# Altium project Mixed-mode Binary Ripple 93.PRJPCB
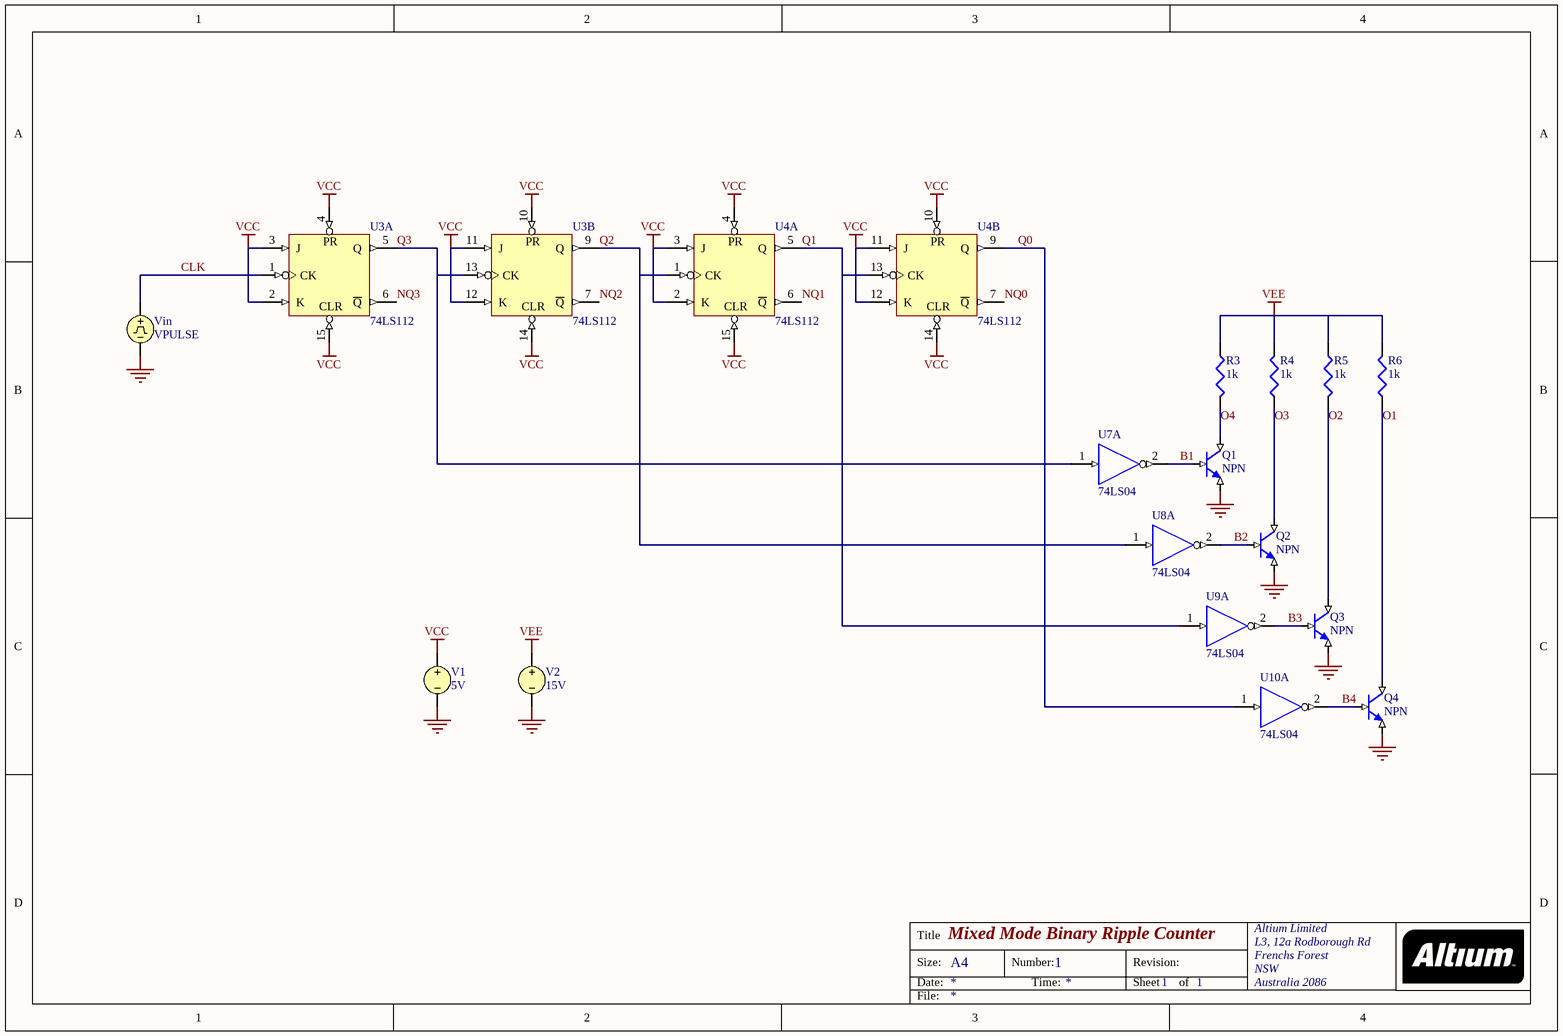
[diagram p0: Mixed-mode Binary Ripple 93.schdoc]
1 sheet, 17 parts. Net scope: global (net labels, ports and power ports of the same name join across sheets).

## Sheet Mixed-mode Binary Ripple 93.schdoc: Mixed Mode Binary Ripple Counter
size A4; Organization: Altium Limited; Address1: L3, 12a Rodborough Rd; Address2: Frenchs Forest; Address3: NSW; Address4: Australia 2086; DocumentNumber: 1; SheetNumber: 1; SheetTotal: 1

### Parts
Q1  NPN
Q2  NPN
Q3  NPN
Q4  NPN
R3  1k
R4  1k
R5  1k
R6  1k
U3  74LS112  (parts A,B of 2)
U4  74LS112  (parts A,B of 2)
U7  74LS04  (part A of 6)
U8  74LS04  (part A of 6)
U9  74LS04  (part A of 6)
U10  74LS04  (part A of 6)
V1  5V
V2  15V
Vin  VPULSE

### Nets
GND: Q1.3(E) Q2.3(E) Q3.3(E) Q4.3(E) U3.8(GND) U4.8(GND) U7.7(GND) U8.7(GND) U9.7(GND) U10.7(GND) V1.2 V2.2 Vin.2
VCC: U3.2(K) U3.3(J) U3.4(PR) U3.10(PR) U3.11(J) U3.12(K) U3.14(CLR) U3.15(CLR) U3.16(VCC) U4.2(K) U4.3(J) U4.4(PR) U4.10(PR) U4.11(J) U4.12(K) U4.14(CLR) U4.15(CLR) U4.16(VCC) U7.14(VCC) U8.14(VCC) U9.14(VCC) U10.14(VCC) V1.1
VEE: R3.2(BOT) R4.1(TOP) R5.2(BOT) R6.1(TOP) V2.1
B1: Q1.2(B) U7.2(Y)
B2: Q2.2(B) U8.2(Y)
B3: Q3.2(B) U9.2(Y)
B4: Q4.2(B) U10.2(Y)
CLK: U3.1(CK) Vin.1
NQ0: U4.7(~{Q})
NQ1: U4.6(~{Q})
NQ2: U3.7(~{Q})
NQ3: U3.6(~{Q})
O1: Q4.1(C) R6.2(BOT)
O2: Q3.1(C) R5.1(TOP)
O3: Q2.1(C) R4.2(BOT)
O4: Q1.1(C) R3.1(TOP)
Q0: U4.9(Q) U10.1(A)
Q1: U4.5(Q) U4.13(CK) U9.1(A)
Q2: U3.9(Q) U4.1(CK) U8.1(A)
Q3: U3.5(Q) U3.13(CK) U7.1(A)

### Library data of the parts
Q1-Q4 = NPN: NPN BJT
R3-R6 = RES: Resistor
U3 U4 = 74LS112: Dual J-K Negative-Edge-Triggered Flip-Flop with Clear and Preset
U7-U10 = 74LS04: Hex Inverter
V1 V2 = VSRC: Voltage Source
Vin = VPULSE: Pulse Voltage Source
